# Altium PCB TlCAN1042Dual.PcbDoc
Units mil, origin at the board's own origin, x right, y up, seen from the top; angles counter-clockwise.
Board outline 1800 x 1400 mil, 4 copper layers (Top Layer, Signal Layer 1, Signal Layer 2, Bottom Layer), stack 84.834 mil thick; 33 components, 20 nets, 97 pads, 26 vias.
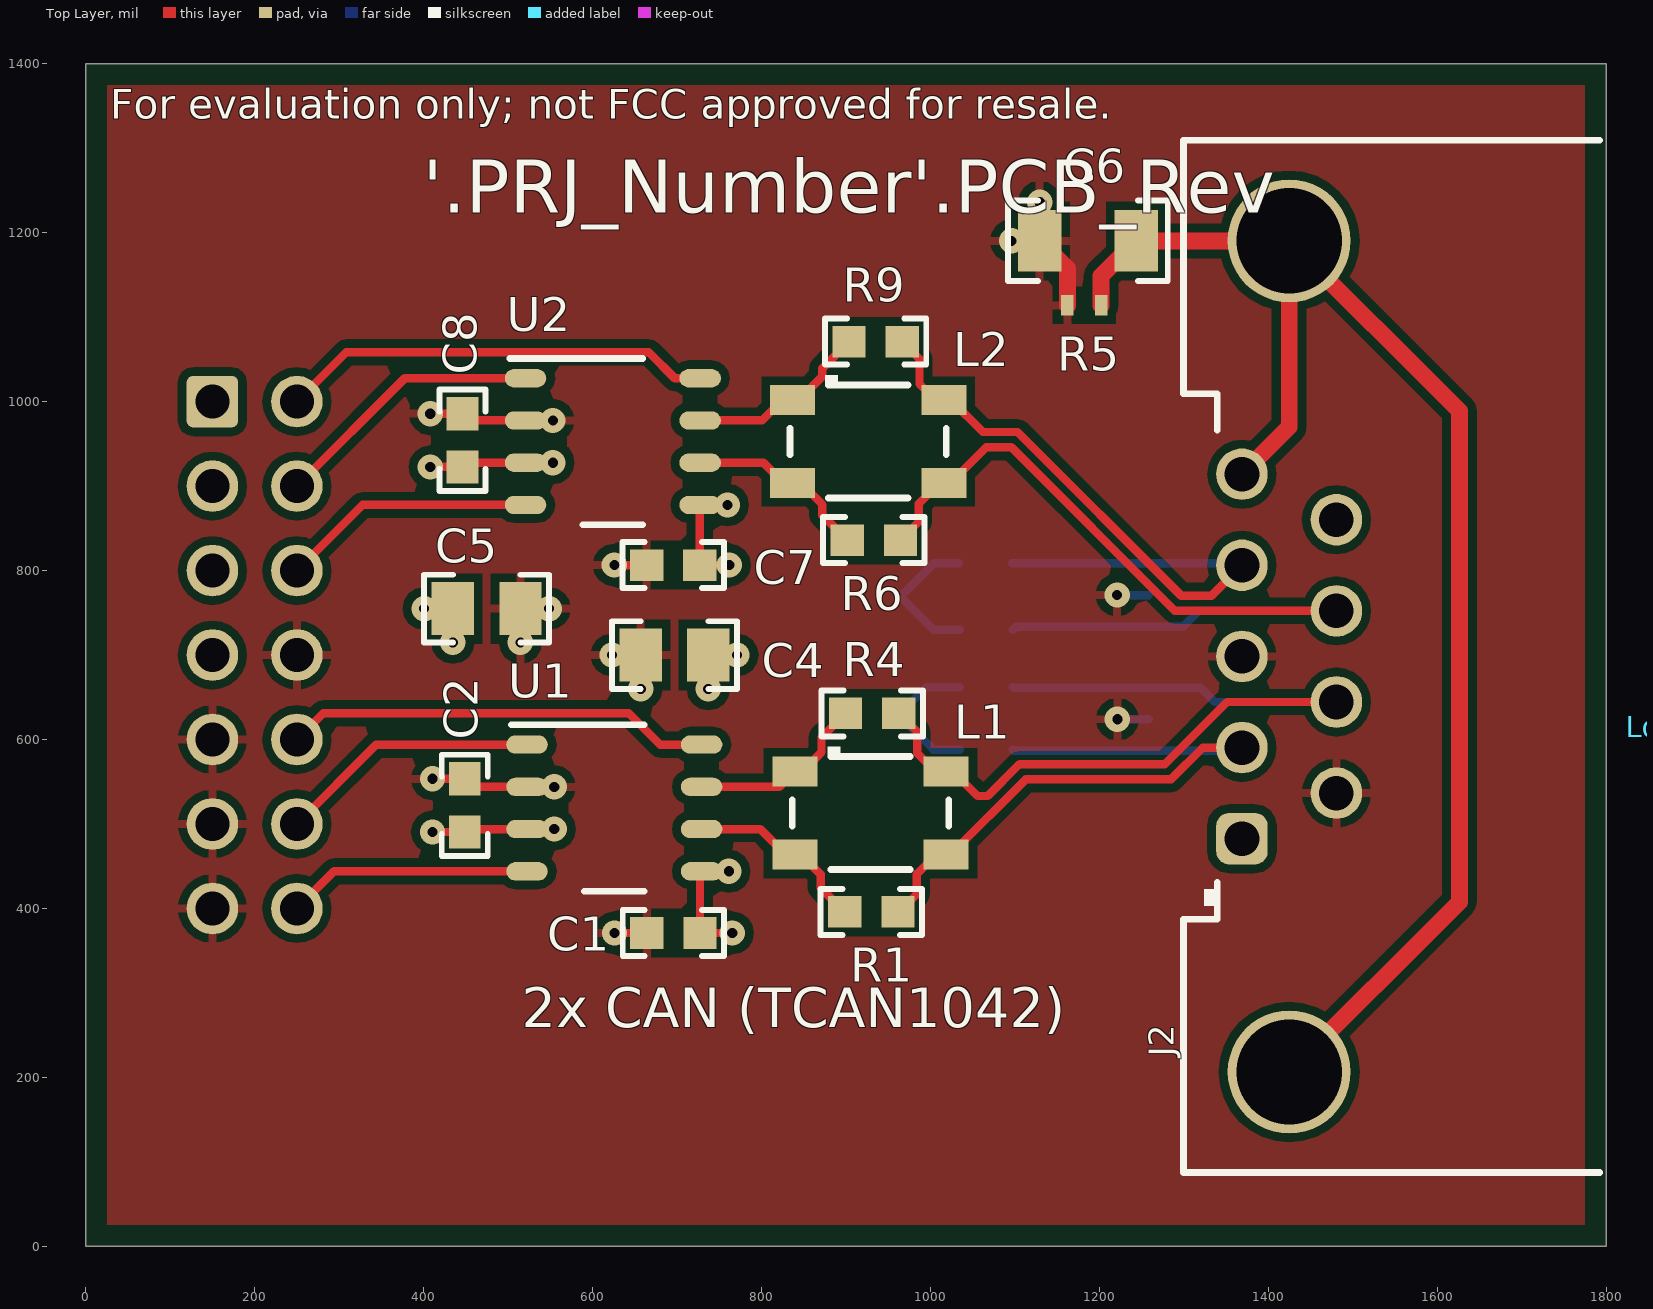
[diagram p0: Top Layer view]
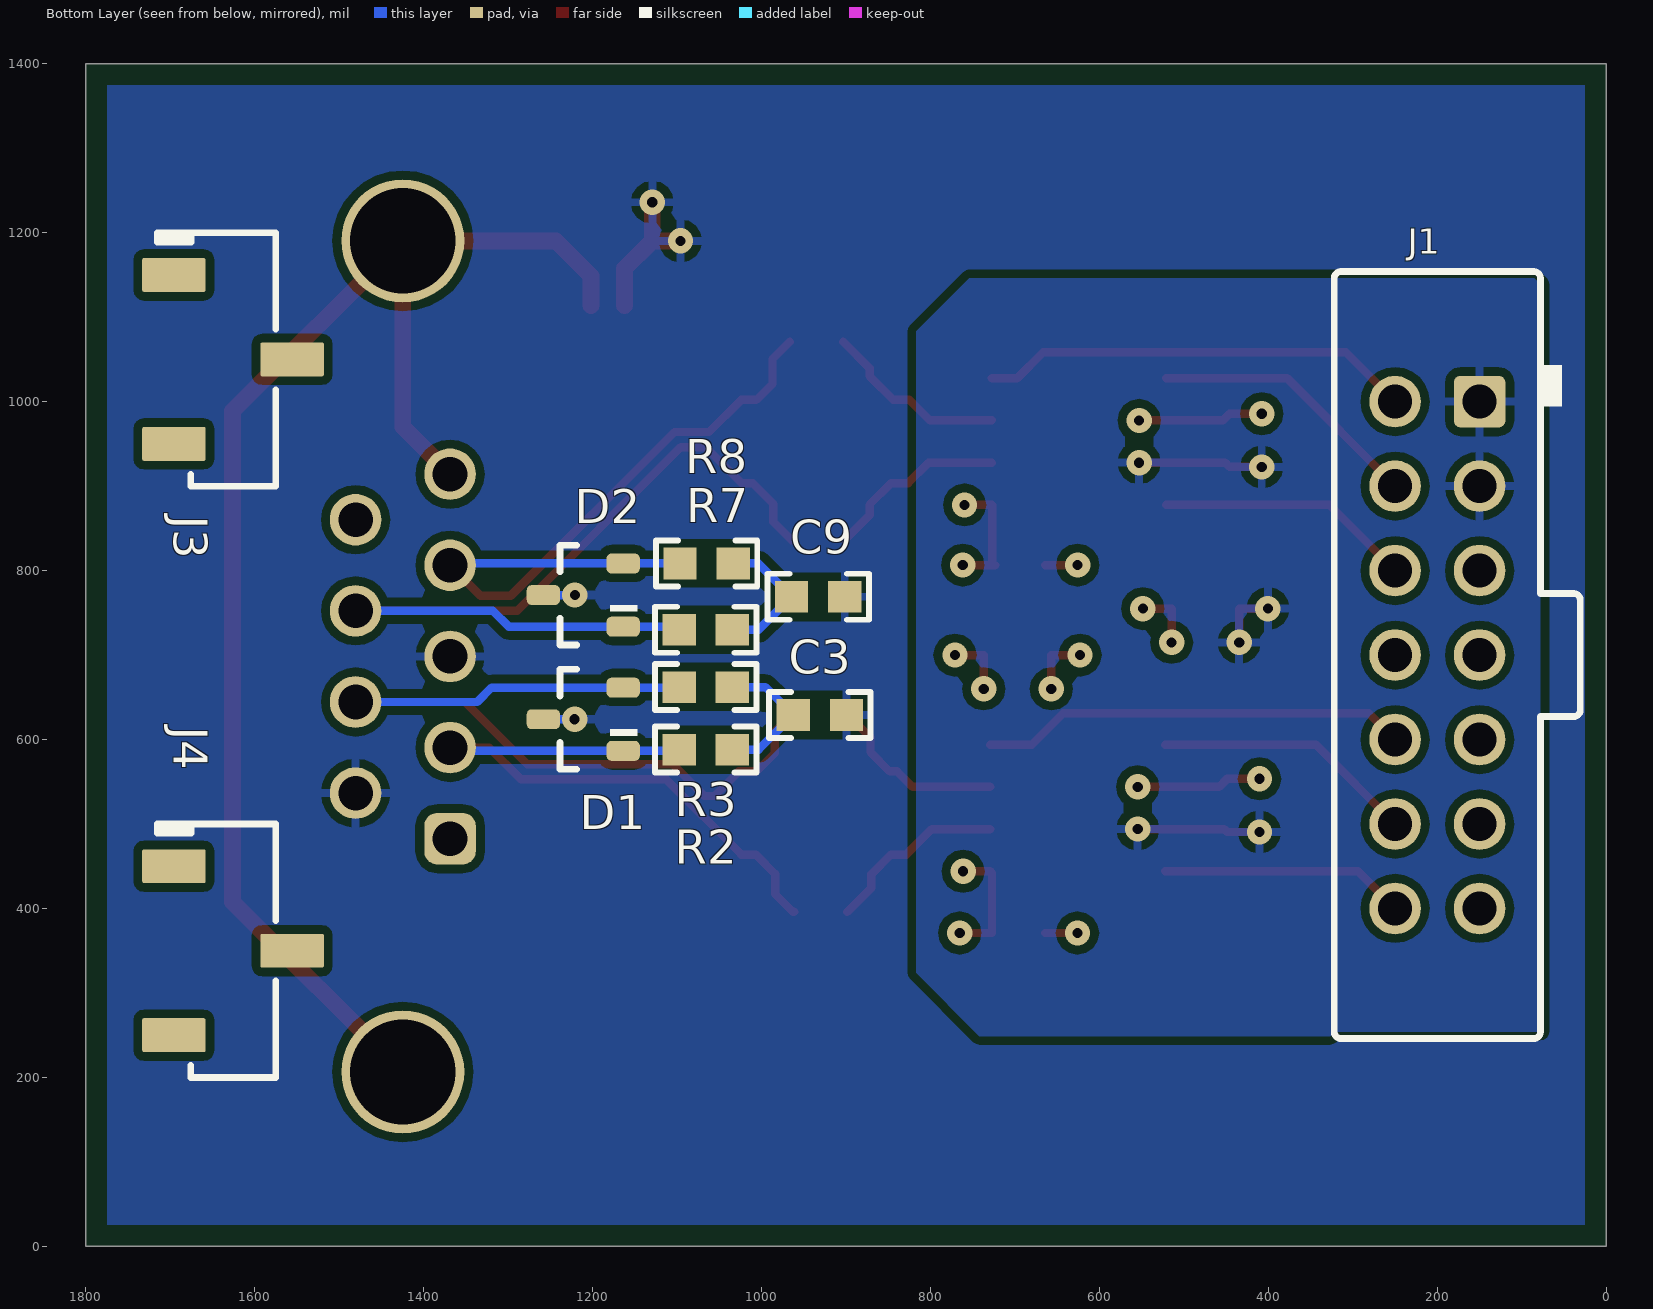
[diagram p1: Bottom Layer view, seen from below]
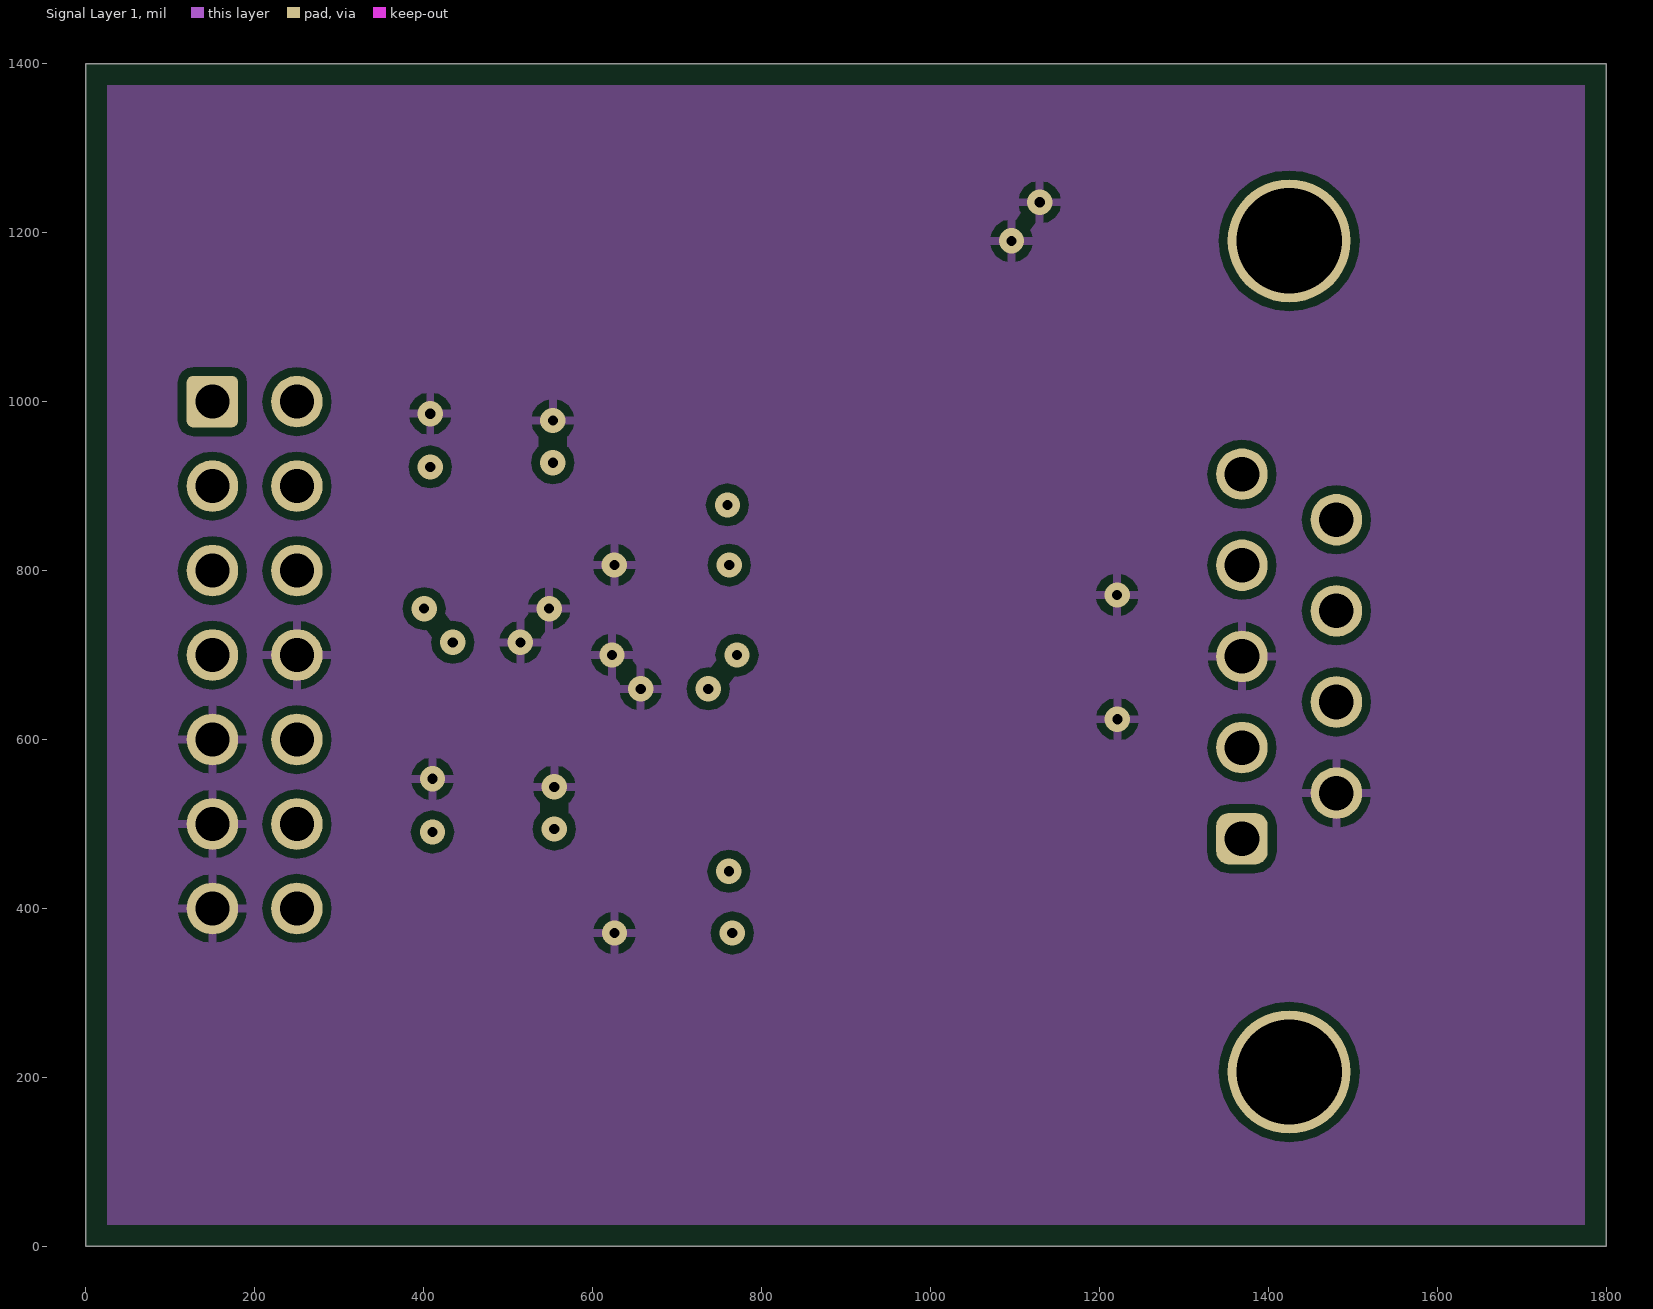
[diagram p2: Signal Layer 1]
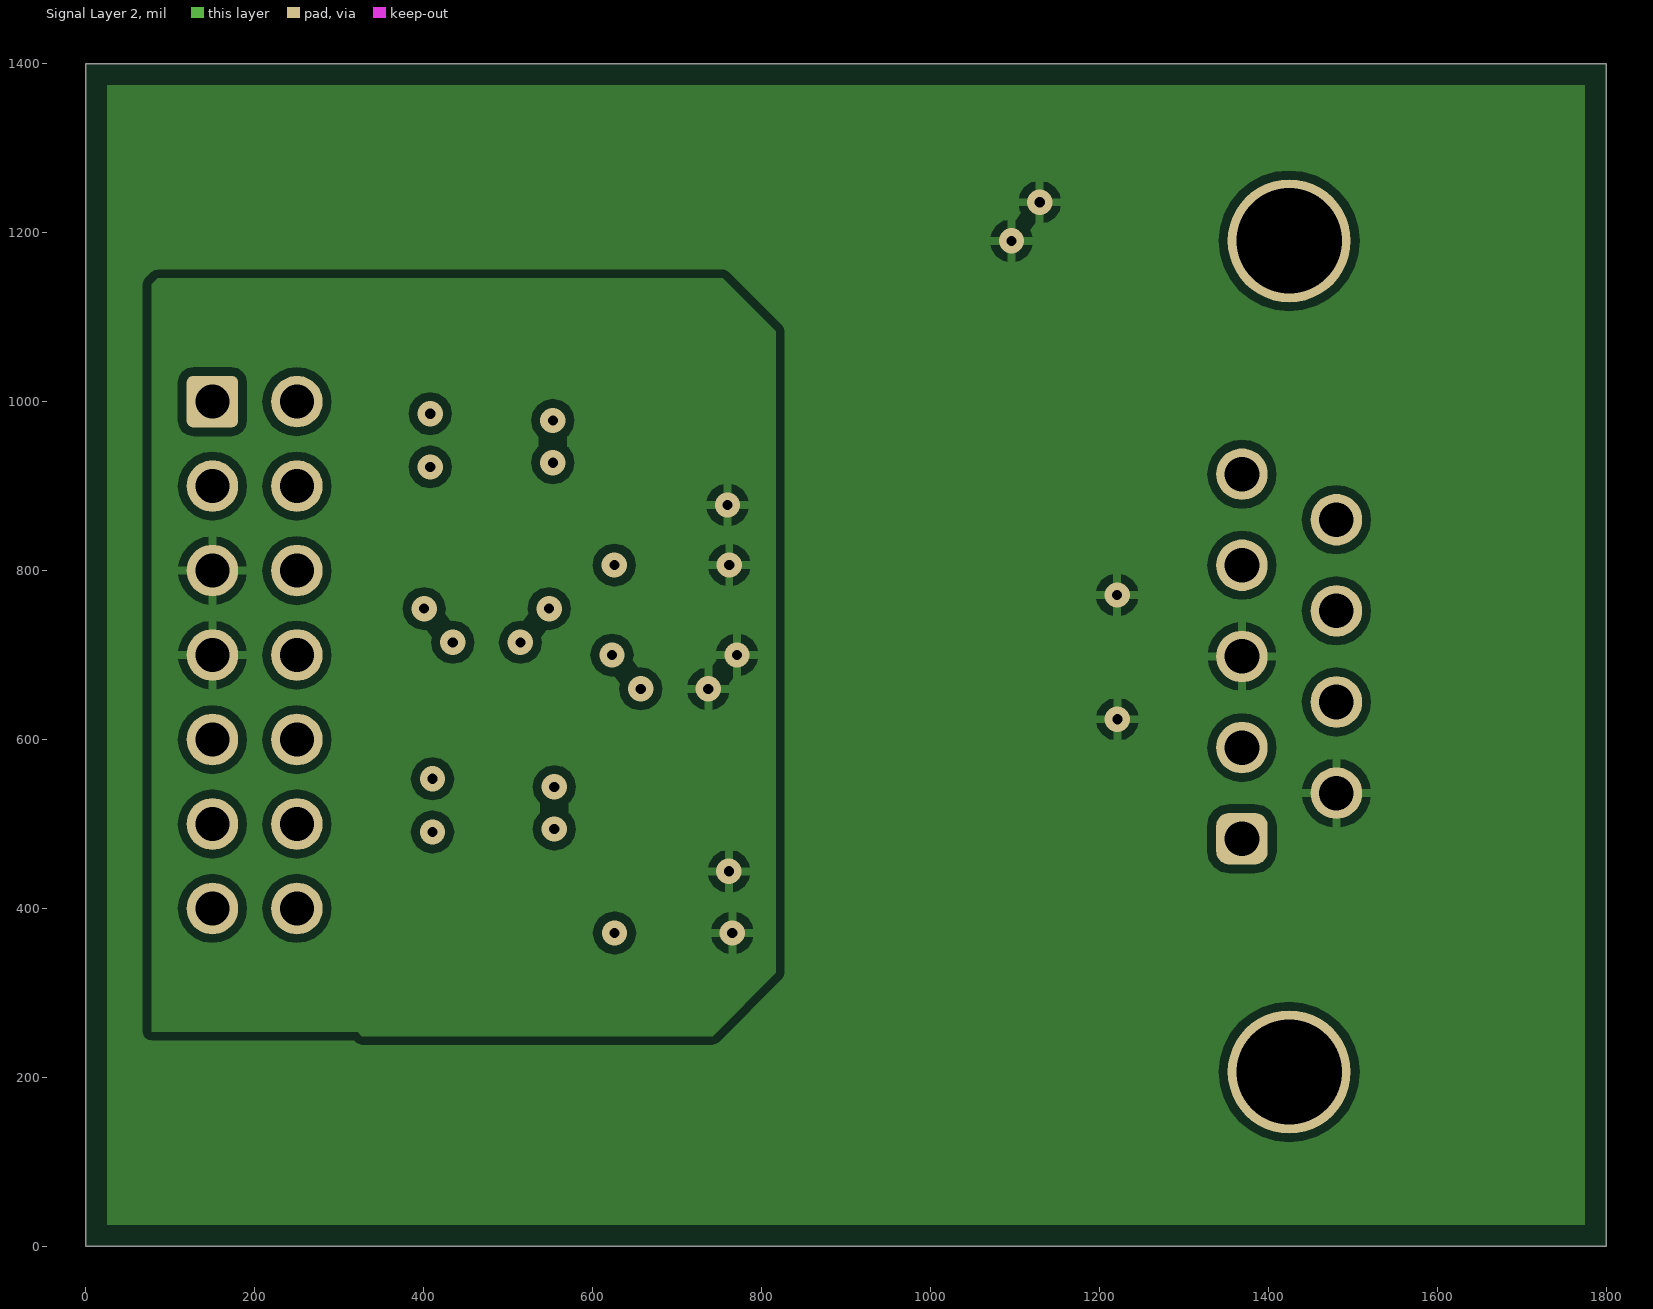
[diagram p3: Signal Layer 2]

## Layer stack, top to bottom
Top Solder: solder mask 0.4, Solder Resist, Dk 3.5
Top Layer: signal copper 1.4
Dielectric 2: dielectric 10, Dk 4.2
Signal Layer 1: signal copper 1.417
Dielectric1: core 59.2, FR-4, Dk 4.8
Signal Layer 2: signal copper 1.417
Dielectric 3: dielectric 10, Dk 4.2
Bottom Layer: signal copper 1.4
Bottom Solder: solder mask 0.4, Solder Resist, Dk 3.5

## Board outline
0,0 1800,0 1800,1400 0,1400

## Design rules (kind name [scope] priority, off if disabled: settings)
AcuteAngle [All] p1: minimum=4.50000000000000E+0001 checktracksonly=FALSE
AssemblyTestPointUsage [All] p1: valid=2
BoardOutlineClearance BoardOutlineClearance_MountingHoles [OnCopper and InComponentClass('Mounting Holes')] p1: gap=39.37 ignorepadtopadclearanceinfootprint=FALSE
BoardOutlineClearance BoardOutlineClearance_Poly [OnCopper and IsPoly] p2: gap=25 ignorepadtopadclearanceinfootprint=FALSE
BoardOutlineClearance [OnCopper and Not InComponentClass('Logo') and not InComponentClass('FiducialMark') and not InRegion(1000,500,4000,800) and not InPoly] p3: gap=75 ignorepadtopadclearanceinfootprint=FALSE
Clearance Clearance_Keepouts [((IsTrack Or IsArc) And Not InPoly) And IsFree and IsKeepOut vs ((IsTrack Or IsArc) And Not InPoly) And IsFree and IsKeepOut] p1: gap=0 ignorepadtopadclearanceinfootprint=FALSE
Clearance Clearance_Poly [InPolygon] p2: gap=10 ignorepadtopadclearanceinfootprint=TRUE
Clearance Clearance_FiducialMark [IsKeepOut and InComponentClass('FiducialMark') vs IsPad and InComponentClass('FiducialMark')] p3: gap=0 ignorepadtopadclearanceinfootprint=FALSE
Clearance [All] p4: gap=7.87 ignorepadtopadclearanceinfootprint=TRUE
ComponentClearance ComponentClearance_MountingHoles_FiducialMarks [InComponentClass('Mounting Holes') vs InComponentClass('FiducialMark')] p1: gap=50 collisioncheckmode=3 verticalgap=10 showdistances=FALSE
ComponentClearance ComponentClearance_Shunt [InComponentClass('Header') vs InComponentClass('Shunt')] p2: gap=0 collisioncheckmode=3 verticalgap=0 showdistances=FALSE
ComponentClearance ComponentClearance_Logo [InComponentClass('Logo')] p3: gap=50 collisioncheckmode=3 verticalgap=10 showdistances=FALSE
ComponentClearance ComponentClearance_ScrewToNut [(HasFootprint('NY PMS 440 0025 PH')) vs (HasFootprint('Keystone_1902C'))] p4: gap=5 collisioncheckmode=3 verticalgap=10 showdistances=FALSE
ComponentClearance ComponentClearance_MountingHoles [InComponentClass('Mounting Holes')] p5: gap=250 collisioncheckmode=3 verticalgap=100000 showdistances=FALSE
ComponentClearance ComponentClearance_SmallPassives [HasFootprint('0201*') or HasFootprint('0402*') or HasFootprint('0508') or HasFootprint('0603*') or HasFootprint('0612') or HasFootprint('0805*') or HasFootprint('0815*') or HasFootprint('0830*') or HasFootprint('1206*') or HasFootprint('1210*') or HasFootprint('1808*') or HasFootprint('1812*') or HasFootprint('1825*') or HasFootprint('2010*') or HasFootprint('2220*') or HasFootprint('2225*') or HasFootprint('2512*') or HasFootprint('2728*') or HasFootprint('3518*') vs HasFootprint('0201*') or HasFootprint('0402*') or HasFootprint('0508') or HasFootprint('0603*') or HasFootprint('0612') or HasFootprint('0805*') or HasFootprint('0815*') or HasFootprint('0830*') or HasFootprint('1206*') or HasFootprint('1210*') or HasFootprint('1808*') or HasFootprint('1812*') or HasFootprint('1825*') or HasFootprint('2010*') or HasFootprint('2220*') or HasFootprint('2225*') or HasFootprint('2512*') or HasFootprint('2728*') or HasFootprint('3518*')] p6: gap=14.96 collisioncheckmode=3 verticalgap=10 showdistances=FALSE
ComponentClearance ComponentClearance_THtoSMT [IsThruComponent vs IsSMTComponent] p7: gap=40 collisioncheckmode=3 verticalgap=30 showdistances=FALSE
ComponentClearance ComponentClearance_THtoTH [IsThruComponent vs IsThruComponent] p8: gap=30 collisioncheckmode=3 verticalgap=30 showdistances=FALSE
ComponentClearance [All] p9: gap=30 collisioncheckmode=3 verticalgap=10 showdistances=FALSE
DiffPairsRouting [All] p1: maxlimit=100 minlimit=10 mostfreqgap=10 toplayer_minwidth=15 toplayer_maxwidth=15 toplayer_prefwidth=15 midlayer1_minwidth=15 midlayer1_maxwidth=15 midlayer1_prefwidth=15 midlayer2_minwidth=15 midlayer2_maxwidth=15 midlayer2_prefwidth=15 bottomlayer_minwidth=15 bottomlayer_maxwidth=15 bottomlayer_prefwidth=15 maxuncoupledlength=1000
FabricationTestPointUsage TestPointUsage [All] p1: valid=2 allowmultiple=FALSE
FabricationTestpoint Testpoint [All] p1: side=3 testpointundercomponent=TRUE minsize=40 maxsize=100 preferedsize=60 minholesize=0 maxholesize=40 preferedholesize=32 testpointgrid=1 allowsidetop=TRUE allowsidebottom=TRUE usegrid=TRUE gridtolerance=0.01
FanoutControl Fanout_LCC [IsLCC] p1: bgadir=Out bgaviamode=Centered fanoutstyle=Auto fanoutdirection=Alternating viagrid=1 // Fanout_LCC (Default Rule)
FanoutControl Fanout_BGA [IsBGA] p2: bgadir=Out bgaviamode=Centered fanoutstyle=Auto fanoutdirection=Alternating viagrid=1 // Fanout_BGA (Default Rule)
FanoutControl Fanout_Default [All] p4: bgadir=Out bgaviamode=Centered fanoutstyle=Auto fanoutdirection=Alternating viagrid=1 // Fanout_Default (Default Rule)
FanoutControl Fanout_Small [(CompPinCount < 5)] p5: bgadir=Out bgaviamode=Centered fanoutstyle=Auto fanoutdirection=OutThenIn viagrid=1 // Fanout_Small (Default Rule)
HoleSize [All] p1: absolutevalues=TRUE maxlimit=251 minlimit=7.87 maxpercent=80.000 minpercent=20.000
MinimumAnnularRing MinimumAnnularRing_ThermalPadVias [IsVia and InAnyComponent] p1: minimumring=5.91
MinimumAnnularRing [All] p2: minimumring=7.87
MinimumSolderMaskSliver MinimumSolderMaskSliver_Logo [InComponentClass('Logo') vs InComponentClass('Logo')] p1: minsoldermaskwidth=0.7
MinimumSolderMaskSliver [All] p2: minsoldermaskwidth=3.94
PlaneConnect [All] p1: planeconnectstyle=Relief reliefexpansion=10 reliefentries=4 reliefconductorwidth=10 reliefairgap=10
PolygonConnect [All] p1: connectstyle=Relief reliefconductorwidth=10 reliefentries=4 polygonreliefangle="90 Angle" airgapwidth=10
RoutingVias ThermalPadVias [IsVia and InAnyComponent] p1: holewidth=7.87 width=19.68 viastyle="Through Hole" minholewidth=7.87 minwidth=19.68 maxholewidth=12.99 maxwidth=23.62
RoutingVias [All] p2: holewidth=16 width=34 viastyle="Through Hole" minholewidth=7.87 minwidth=26 maxholewidth=40 maxwidth=65
SilkToBoardRegionClearance [Not ((IsComment or IsDesignator) And (Hide <> 'False')) and not InRegion(1000,500,4000,800)] p1:
SilkToSilkClearance SilkToSilkClearance_Pb-FreeLogo [(HasFootprint('Pb-Free_Overlay_Medium') OR HasFootprint('Pb-Free_Overlay_Small')) vs (HasFootprint('Pb-Free_Overlay_Medium') OR HasFootprint('Pb-Free_Overlay_Small'))] p1: silktosilkclearance=0
SilkToSilkClearance [All] p2: silktosilkclearance=3.94
SilkToSolderMaskClearance SilkToComponentPadClearance [(IsPad or IsFill or IsRegion) and InAnycomponent] p1: minsilkscreentomaskgap=5 clearancetoexposedcopper=TRUE
SilkToSolderMaskClearance "Silk to Solder Mask Opening" [All] p2: minsilkscreentomaskgap=3.94 clearancetoexposedcopper=FALSE
SolderMaskExpansion [All] p1: expansion=1.97
UnRoutedNet [All] p1: checkbadconnections=TRUE
Width [All] p1: maxlimit=100 minlimit=6 preferedwidth=10 checkconnectedcopper=TRUE
14 further rules are at their usual default settings.

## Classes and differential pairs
component class AssemblyNote: ZZ1 ZZ2 ZZ3 ZZ4

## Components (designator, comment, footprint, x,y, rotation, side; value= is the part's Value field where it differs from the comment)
C1 "GRM188R72A104KA35D" 0603 695.69,371 r180 top value=0.1uF
C2 "GRM188R72A104KA35D" 0603 448.69,522 r90 top value=0.1uF
C3 "CGA3E2X7R2A472K080AA" 0603 931,629 r0 bottom value=4700pF
C4 "CL21B106KOQNNNE" 0805_HV 697,700 r180 top value=10uF
C5 "CL21B106KOQNNNE" 0805_HV 474.57,755 r0 top value=10uF
C6 "12061C103JAT2A" 1206 1186.39,1190.3 r180 top value=0.01uF
C7 "GRM188R72A104KA35D" 0603 695.52,806.52 r180 top value=0.1uF
C8 "GRM188R72A104KA35D" 0603 446.03,954.18 r90 top value=0.1uF
C9 "CGA3E2X7R2A472K080AA" 0603 933,769 r0 bottom value=4700pF
D1 "NUP2105LT1G" SOT-23 1211,624 r0 bottom value=24V
D2 "NUP2105LT1G" SOT-23 1211,771 r0 bottom value=24V
J1 "SFH11-PBPC-D07-ST-BK" Sullins_SFH11-xxxC-D07-ST-BK 200,700 r270 bottom locked
J2 "5747840-5" TE_5747840-5 1800,698.37 r90 top locked
J3 "SSM-103-S-SV" Samtec_SSM-103-x-SV 1625.62,1050 r270 bottom locked
J4 "SSM-103-S-SV" Samtec_SSM-103-x-SV 1625.62,350 r270 bottom locked
L1 "ACT45B-101-2P-TL003" ACT45B 929,513 r0 top value=100uH
L2 "ACT45B-101-2P-TL003" ACT45B 926.2,952.77 r0 top value=100uH
Logo2 "FCC disclaimer" FCC_disclaimer 1876,615 r90 top
R1 "RMCF0603ZT0R00" 0603 930,396 r0 top value=0
R2 "CRCW060360K4FKEA" 0603 1066,588 r0 bottom value=60.4k
R3 "CRCW060360K4FKEA" 0603 1066,662 r180 bottom value=60.4k
R4 "RMCF0603ZT0R00" 0603 931,631 r0 top value=0
R5 "ERJ-2RKF1004X" 0402S 1182,1114 r0 top value=1.00Meg
R6 "RMCF0603ZT0R00" 0603 933,836 r0 top value=0
R7 "CRCW060360K4FKEA" 0603 1066,730 r0 bottom value=60.4k
R8 "CRCW060360K4FKEA" 0603 1065,808.4 r180 bottom value=60.4k
R9 "RMCF0603ZT0R00" 0603 935,1071 r0 top value=0
U1 "TCAN1042GVDRQ1" D0008A_L 625.71,519 r0 top
U2 "TCAN1042GVDRQ1" D0008A_L 624,952.68 r0 top
ZZ1 "This Assembly Note is for PCB labels only" AssemblyNoteLabel 185,3938 r0 top
ZZ2 "These assemblies are ESD sensitive, ESD precautions shall be observed." AssemblyNote 185,3829.11 r0 top
ZZ3 "These assemblies must be clean and free from flux and all contaminants. Use of no clean flux is not acceptable." AssemblyNote 185,3740.56 r0 top
ZZ4 "These assemblies must comply with workmanship standards IPC-A-610 Class 2, unless otherwise specified." AssemblyNote 185,3652 r0 top

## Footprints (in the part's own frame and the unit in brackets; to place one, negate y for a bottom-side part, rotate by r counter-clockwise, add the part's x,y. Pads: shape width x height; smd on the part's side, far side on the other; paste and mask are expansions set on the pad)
0402S [mil] "Based on C0402S footprint from PADS legacy"
  rect 15x24 smd: 1(-20,0) 2(20,0)
  body extent -22,-12 22,12, height 24
0603 [mm] "0603 from SM-752 data"
  rect 1x0.95 smd: 1(-0.8,0) 2(0.8,0)
  silkscreen extent -1.52,-0.69 1.52,0.69, body extent -0.87,-0.47 0.87,0.47, height 1
0805_HV [mil] "0805 with 30mil clearance between pads"
  rect 50x63 smd: 1(-40,0) 2(40,0)
  silkscreen extent -74,-40 74,40, body extent -43,-29 43,29, height 57
1206 [mm] "1206 from SM-752 data"
  rect 1.3x1.85 smd: 1(-1.45,0) 2(1.45,0)
  silkscreen extent -2.4,-1.21 2.4,1.21, body extent -1.7,-0.9 1.7,0.9, height 1.35
ACT45B [mm] "SMD, 4-Leads, Body 4.7 x 3.7 mm"
  rect 1.35x0.9 smd: 1(-2.275,1.25) 2(-2.275,-1.25) 3(2.275,-1.25) 4(2.275,1.25)
  silkscreen extent -2.35,-1.7 2.35,2, body extent -2.35,-1.7 2.35,1.7, height 3
AssemblyNote [mil] "Assembly Note"
AssemblyNoteLabel [mil] "Assembly Note for PCB Labels"
D0008A_L [mm] "SOIC, 8-Leads, Body 4.9x3.9mm, Pitch 1.27mm, IPC High Density"
  oval 1.25x0.55 smd: 1(-2.625,1.905) 2(-2.625,0.635) 3(-2.625,-0.635) 4(-2.625,-1.905) 5(2.625,-1.905) 6(2.625,-0.635) 7(2.625,0.635) 8(2.625,1.905)
  silkscreen extent -3.1,-2.5 0.9,2.5, body extent -3,-2.45 3,2.45, height 1.63
FCC_disclaimer [mil]
Samtec_SSM-103-x-SV [mm] "Receptacle, 2.54mm, 3x1, SMT"
  rrect10% 1.02x1.905 smd: 1(-2.54,-1.777) 2(0,1.777) 3(2.54,-1.777)
  silkscreen extent -3.81,-2.27 3.81,1.28, body extent -3.81,-2.29 3.81,2.29, height 7.51
SOT-23 [mm] "SOT23, 3-Leads, Body 2.9x1.3mm, Pitch 0.95mm, Lead Span 2.5mm, IPC Medium Density"
  rrect50% 1x0.6 smd: 1(-1.2,0.95) 2(-1.2,-0.95) 3(1.2,0)
  silkscreen extent -1.62,-1.5 0.7,1.5, body extent -1.16,-1.45 1.21,1.45, height 1
Sullins_SFH11-xxxC-D07-ST-BK [mm] "Receptacle, 2.54mm, 7x2, TH"
  rrect25% 1.55x1.55 hole 1.02: 1(-7.62,1.27)
  round 1.55 hole 1.02: 2(-7.62,-1.27) 3(-5.08,1.27) 4(-5.08,-1.27) 5(-2.54,1.27) 6(-2.54,-1.27) 7(0,1.27) 8(0,-1.27) 9(2.54,1.27) 10(2.54,-1.27) 11(5.08,1.27) 12(5.08,-1.27) 13(7.62,1.27) 14(7.62,-1.27)
  silkscreen extent -11.53,-3.1 11.53,4.3, body extent -11.53,-3.1 11.53,4.3, height 8.71
TE_5747840-5 [mm] "D-Sub, 2.74mm, 9 Position, R/A, TH"
  rrect50% 1.55x1.55 hole 1.04: 1(-5.48,10.954)
  round 1.55 hole 1.04: 2(-2.74,10.954) 3(0,10.954) 4(2.74,10.954) 5(5.48,10.954) 6(-4.11,8.114) 7(-1.37,8.114) 8(1.37,8.114) 9(4.11,8.114)
  round 3.7 hole 3.17: 10(12.495,9.534) 11(-12.495,9.534)
  silkscreen extent -15.52,0.2 15.52,12.71, body extent -15.52,-5.89 15.52,12.71, height 12.55

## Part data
C1 C2 C7 C8: library part CMP-0007469-4, "CAP, CERM, 0.1 uF, 100 V, +/- 10%, X7R, 0603", Cap_Case=0603, Manufacturer=MuRata, Supplier Part Number 1=490-3285-1-ND, TempCo=X7R, Tolerance_%=10%, Value1=Unknown, Value2=100V, ValueDisplayed=0.1uF
C3 C9: library part CMP-0007088-4, "CAP, CERM, 4700 pF, 100 V, +/- 10%, X7R, AEC-Q200 Grade 1, 0603", Cap_Case=0603, Manufacturer=TDK, Supplier Part Number 1=445-5810-1-ND, TempCo=X7R, Tolerance_%=10%, Value1="0.469862 ohm", Value2=100V, ValueDisplayed=4700pF
C4 C5: library part CMP-0007995-2, "CAP, CERM, 10 uF, 16 V, +/- 10%, X7R, 0805", Cap_Case=0805, Manufacturer="Samsung Electro-Mechanics", TempCo=X7R, Tolerance_%=10%, Value1=Unknown, Value2=16V, ValueDisplayed=10uF
C6: library part CMP-0008484-2, "CAP, CERM, 0.01 uF, 100 V, +/- 5%, X7R, 1206", Cap_Case=1206, Manufacturer=AVX, Supplier Part Number 1=478-3783-1-ND, TempCo=X7R, Tolerance_%=5%, Value1="0.119 ohm", Value2=100V, ValueDisplayed=0.01uF
D1 D2: library part CMP-0005919-2, "Diode, TVS, Bi, 24 V, SOT-23", Manufacturer="ON Semiconductor", Power_W=350mW, Supplier Part Number 1=NUP2105LT1GOSCT-ND, Value1=0.35W
J1: library part CMP-0054668-1, "Receptacle, 2.54mm, 7x2, Gold, Black, TH", Color=Black, Current_A=3A, Manufacturer="Sullins Connector Solutions", Supplier Part Number 1=S9195-ND, Voltage_V=1kV
J2: library part CMP-0054938-4, "D-Sub, 2.74mm, 9 Position, R/A, TH", Color=Black, Manufacturer="TE Connectivity", Supplier Part Number 1=A32093-ND
J3 J4: library part CMP-0078183-1, "Receptacle, 2.54mm, 3x1, Gold with Tin tail, SMT", Color=Black, Current_A=5.2A, Manufacturer=Samtec, Supplier Part Number 1=SAM1152-03-ND, Voltage_V=405V
L1 L2: library part CMP-0062430-2, "Inductor, Ferrite, 100 uH, 0.15 A, 2 ohm, SMD", Manufacturer=TDK, Supplier Part Number 1=445-3959-1-ND, Value1="2 ohm", Value2=0.15A, ValueDisplayed=100uH
Logo2: library part CMP-0074847-1, "FCC_disclaimer"
R1 R4 R6 R9: library part CMP-0023343-3, "RES, 0, 1%, 0.1 W, AEC-Q200 Grade 0, 0603", Manufacturer="Stackpole Electronics Inc", Power_W=100mW, Supplier Part Number 1=RMCF0603ZT0R00CT-ND, TempCo=ppm/C, Tolerance_%=1%, Value2=0.1W, Value_Code=0
R2 R3 R7 R8: library part CMP-0022532-4, "RES, 60.4 k, 1%, 0.1 W, AEC-Q200 Grade 0, 0603", Manufacturer=Vishay-Dale, Power_W=100mW, Supplier Part Number 1=541-60.4KHCT-ND, TempCo="100 ppm/C", Tolerance_%=1%, Value2=0.1W, Value_Code=60k4, ValueDisplayed=60.4k
R5: library part CMP-0026660-1, "RES, 1.00 M, 1%, 0.1 W, 0402", Manufacturer=Panasonic, Power_W=100mW, Supplier Part Number 1=P1.00MLCT-ND, TempCo="100 ppm/C", Tolerance_%=1%, Value2=0.1W, Value_Code=1M00, ValueDisplayed=1.00M
U1 U2: library part CMP-0075989-1, "Automotive Fault Protected CAN Transceiver With Flexible Data-Rate, D0008A (SOIC-8)", Alternate Manufacturer="Texas Instruments", Alternate PartNumber=TCAN1042GVDQ1
ZZ1: library part CMP-0003616-3
ZZ2: library part CMP-0077236-1
ZZ3: library part CMP-0077237-1
ZZ4: library part CMP-0077238-1

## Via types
v1: diameter 30, hole 12, Top Layer to Bottom Layer, tented both sides, 26 vias

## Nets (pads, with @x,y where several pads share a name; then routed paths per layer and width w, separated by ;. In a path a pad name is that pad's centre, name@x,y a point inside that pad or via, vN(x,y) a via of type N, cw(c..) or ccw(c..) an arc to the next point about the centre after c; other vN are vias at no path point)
+3V3: C1.1 C4.1 C7.1 J1.5 J1.7 U1.5 U2.5 | length 360.1
  Top Layer w10: C7.1@723.57,806.52 v1(761.77,806.52) ; C7.1 727.02,877.36 U2.5 v1(759.68,877.68) ; v1(737,660) C4.1 v1(771,700) ; v1(761.4,444) U1.5 727.19,442.13 C1.1 v1(765.39,371)
+5V0: C2.1 C5.1 C8.1 J1.1 J1.3 U1.3 U2.3 | length 366.9
  Top Layer w10: v1(400.57,755) C5.1 v1(434.57,715) ; v1(407.83,922.68) C8.1 451.03,927.68 U2.3 v1(552.99,927.68) ; v1(410.5,490.5) C2.1 452.19,494 U1.3 v1(554.7,494)
CANH_BUS: D1.2 J2.7 L1.4 R3.1 R4.2 | length 1009.9
  Top Layer w10: R4.2 984.49,609 984.49,583.53 1005.81,562.21 L1.4 1026.79,562.21 1055.86,533.14 1067.86,533.14 1105.6,570.87 1277.51,570.87 1351.06,644.43 J2.7
  Bottom Layer w10: R3.1 1098.09,661.4 D1.2 1319.6,661.4 1336.57,644.43 J2.7
CANH_BUS2: D2.2 J2.4 L2.4 R8.1 R9.2 | length 832.2
  Top Layer w10: R9.2 987,1050.5 987,1021 1006.02,1001.98 L2.4 1024.02,1001.98 1062,964 1103,964 1296.82,770.18 1332.67,770.18 J2.4
  Bottom Layer w10: R8.1 D2.2 1366.57,808.4 J2.4
CANL_BUS: D1.1 J2.2 L1.3 R1.2 R2.2 | length 775.1
  Top Layer w10: R1.2 962.72,396 984,417.28 984,441 1006.79,463.79 L1.3 1023.79,463.79 1113,553 1284.91,553 1322.4,590.49 J2.2
  Bottom Layer w10: R2.2 1098.9,586.6 D1.1 1364.84,586.6 J2.2
CANL_BUS2: D2.1 J2.8 L2.3 R6.2 R7.2 | length 1046.8
  Top Layer w10: R6.2 986,857.5 986,879 1010.56,903.56 L2.3 1023.56,903.56 1066.13,946.13 1095.6,946.13 1289.42,752.31 J2.8
  Bottom Layer w10: R7.2 1101.09,733.6 D2.1 1299.2,733.6 1317.9,752.31 J2.8
GND: C1.2 C2.2 C3.1 C4.2 C5.2 C6.2 C7.2 C8.2 C9.1 D1.3 D2.3 J1.8 J1.9 J1.11 J1.13 J2.3 J2.6 R5.1 U1.2 U2.2 | length 764.4
  Top Layer w10: v1(407.83,985.68) C8.2 454.02,977.68 U2.2 v1(552.99,977.68) ; v1(410.5,553.5) C2.2 458.19,544 U1.2 v1(554.7,544) ; v1(514.57,715) C5.2 v1(548.57,755) ; v1(623,700) C4.2 v1(657,660) ; v1(625.83,806.52) C7.2 ; v1(626,371) C1.2
  Top Layer w20: v1(1095.89,1190.3) C6.2 ; v1(1129.31,1235.97) C6.2 ; R5.1 1162,1157.6 C6.2
  Bottom Layer w10: v1(1221,771) D2.3 ; v1(1221.24,624) D1.3@1258.49,624
NetC3_2: C3.2 R2.1 R3.2 | length 174.7
  Bottom Layer w10: R2.1 1003.5,588 C3.2 995.5,662 R3.2
NetC9_2: C9.2 R7.1 R8.2 | length 171.5
  Bottom Layer w10: R8.2 1003.9,808.4 C9.2 1003.5,730 R7.1
NetL1_1: L1.1 R4.1 U1.7 | length 216.8
  Top Layer w10: U1.7 821.22,544 L1.1 848.29,562.21 871.02,584.94 871.02,602.51 R4.1
NetL1_2: L1.2 R1.1 U1.6 | length 219.4
  Top Layer w10: U1.6 798.44,494 828.65,463.79 L1.2 846.71,463.79 870.02,440.48 870.02,424.49 R1.1
NetL2_1: L2.1 R9.1 U2.7 | length 220.4
  Top Layer w10: U2.7 800.68,977.68 824.98,1001.98 L2.1 843.98,1001.98 872,1030 872,1039.5 R9.1
NetL2_2: L2.2 R6.1 U2.6 | length 219.5
  Top Layer w10: U2.6 802.32,927.68 826.44,903.56 L2.2 846.44,903.56 871.98,878.02 871.98,865.53 R6.1
nSTB: J1.10 U1.8 | length 507.2
  Top Layer w10: J1.10 281,631 643,631 680,594 U1.8
nSTB2: J1.2 U2.8 | length 514.2
  Top Layer w10: J1.2 308.32,1058.32 666.68,1058.32 697.32,1027.68 U2.8
RxD: J1.14 U1.4 | length 290.6
  Top Layer w10: J1.14 294,444 U1.4
RxD2: J1.6 U2.4 | length 302.8
  Top Layer w10: J1.6 327.68,877.68 U2.4
SHIELD_GND: C6.1 J2.5 J2.10 J2.11 R5.2 | length 1724.6
  Top Layer w20: R5.2 1202,1148.82 C6.1 J2.10 ; J2.5 1424.64,970.02 J2.10 ; J2.11 1626,407.8 1626,988.94 J2.10
TxD: J1.12 U1.1 | length 311.3
  Top Layer w10: J1.12 344,594 U1.1
TxD2: J1.4 U2.1 | length 323.5
  Top Layer w10: J1.4 377.68,1027.68 U2.1
pads on no net: J2.1 J2.9 J3.1 J3.2 J3.3 J4.1 J4.2 J4.3

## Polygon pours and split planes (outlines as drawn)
GND on Bottom Layer "BOTTOM_LAYER_GND_P006" (solid, remove dead copper, pour order 6): 0,1400 0,0 1800,0 1800,1400
+5V0 on Bottom Layer "BOTTOM_LAYER_+5V0_P000" (solid, remove dead copper, pour order 0): 77.95,1146.06 77.95,253.94 322.05,253.94 326.98,249 742,249 817,324 817,1083 754,1146
GND on Signal Layer 1 "SIGNAL_LAYER_1_GND_P004" (solid, remove dead copper, pour order 4): 0,1400 0,0 1800,0 1800,1400
GND on Signal Layer 2 "SIGNAL_LAYER_2_GND_P010" (solid, remove dead copper, pour order 10): 1,1398 1,-2 1801,-2 1801,1398
+3V3 on Signal Layer 2 "SIGNAL_LAYER_2_+3V3_P002" (solid, remove dead copper, pour order 2): 77.95,1146.06 77.95,253.94 322.05,253.94 326.98,249 742,249 817,324 817,1083 754,1146
GND on Top Layer "TOP_LAYER_GND_P008" (solid, remove dead copper, pour order 8): 1,1398 1,-2 1801,-2 1801,1398

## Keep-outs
Keep-Out Layer:
  text ".Layer_Name" at 577,-858.49 h60

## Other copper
Top Layer:
  text ".Layer_Name" at 577,-858.49 h60
Bottom Layer:
  text ".Layer_Name" at 577,-858.49 h60

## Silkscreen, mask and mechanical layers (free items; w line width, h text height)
Top Overlay:
  text "'.PRJ_Number'.PCB_Rev" at 399,1202.58 h108.27
  text "2x CAN (TCAN1042)" at 516,244.16 h80
  text ".Layer_Name" at 577,-858.49 h60
Bottom Overlay:
  text ".Layer_Name" at 577,-858.49 h60
Top Paste:
  text ".Layer_Name" at 577,-858.49 h60
Bottom Paste:
  text ".Layer_Name" at 577,-858.49 h60
Top Solder:
  text ".Layer_Name" at 577,-858.49 h60
  text ".Layer_Name" at 577,-858.49 h60
Bottom Solder:
  text ".Layer_Name" at 577,-858.49 h60
Drill Guide:
  text ".Layer_Name" at 577,-858.49 h60
M1 Board Outline:
  the board outline again, w10
  text ".Layer_Name" at 577,-858.49 h60
M2 Board Dimensions:
  rectangle: 0,-275 125,-150
  rectangle: 125,-400 500,-275
  lines w7: 0,-275 1000,-275 ; 125,-400 125,-150 ; 250,-400 250,-150 ; 500,-400 500,-150 ; 750,-400 750,-150 ; 0,-400 1000,-400 1000,-150 0,-150 0,-400
  text ".Layer_Name" at 577,-858.49 h60
M3 3D STEP Top:
  text ".Layer_Name" at 577,-858.49 h60
M4 3D STEP Bottom:
  text ".Layer_Name" at 577,-858.49 h60
M5 Assembly Top:
  lines w10: -292,-930.17 6308,-930.17 ; -292,-726.83 6310,-726.83 ; -292,-523.5 -292,-1133.5 3713,-1133.5 6310,-1133.5 6310,-523.5 -291.5,-523.5 -291.5,-1133.5 1284,-1133.5 ; 2173,-1133.5 2173,-523.5 ; 3440,-726.83 3440,-523.5 ; 4280,-726.83 4280,-523.5 ; 4902,-1140 4902,-937.17
  text "COMPONENTS MARKED 'DNP' SHOULD NOT BE POPULATED." at 1153.5,-318.5 h60
  text "ASSEMBLY VARIANT:" at 1153,-434 h60
  text ".VariantName" at 2189,-434 h60
  text "PCB VIEWED FROM TOP SIDE" at -228.5,-655.67 h60
  text "BOARD #:" at 2248,-655.67 h60
  text ".PRJ_Number" at 2793.5,-655.67 h60
  text "REV:" at 3638,-655.67 h60
  text ".PCB_Rev" at 3929.5,-655.67 h60
  text "SVN REV:" at 4476,-655.67 h60
  text ".VersionControl_RevNumber" at 4982,-655.67 h60
  text "TID #:" at 2248,-859 h60
  text ".TID" at 2793.5,-859 h60
  text "PLOT NAME =" at -228.5,-1064.34 h60
  text ".plot_File_Name" at 577,-1064.34 h60
  text "GENERATED    :" at 2250,-1064.34 h60
  text ".Print_Date" at 3119.5,-1064.34 h60
  text ".Print_Time" at 3848.5,-1064.34 h60
  text "TEXAS INSTRUMENTS" at 5113,-1064.34 h60
M6 Assembly Bottom:
  lines w10: -292.5,-727.33 6309.5,-727.33 ; -290.5,-930.67 6309.5,-930.67 ; 1115.5,-1140.5 1115.5,-937.67 ; 1737.5,-727.33 1737.5,-524 ; 2577.5,-727.33 2577.5,-524 ; 3844.5,-1134 3844.5,-524 ; 4733.5,-1134 6309,-1134 6309,-524 -292.5,-524 -292.5,-1134 2304.5,-1134 6309.5,-1134 6309.5,-524
  text "COMPONENTS MARKED 'DNP' SHOULD NOT BE POPULATED." at 6102,-318 h60
  text ".VariantName" at 5058,-434 h60
  text "ASSEMBLY VARIANT:" at 6097,-434 h60
  text ".VersionControl_RevNumber" at 1035.5,-656.17 h60
  text "SVN REV:" at 1541.5,-656.17 h60
  text ".PCB_Rev" at 2088,-656.17 h60
  text "REV:" at 2379.5,-656.17 h60
  text ".PRJ_Number" at 3224,-656.17 h60
  text "BOARD #:" at 3769.5,-656.17 h60
  text "PCB VIEWED FROM BOTTOM SIDE" at 6246,-656.17 h60
  text ".TID" at 3224,-859.5 h60
  text "TID #:" at 3769.5,-859.5 h60
  text "TEXAS INSTRUMENTS" at 904.5,-1064.84 h60
  text ".Print_Time" at 2169,-1064.84 h60
  text ".Print_Date" at 2898,-1064.84 h60
  text "GENERATED    :" at 3767.5,-1064.84 h60
  text ".plot_File_Name" at 5440.5,-1064.84 h60
  text "PLOT NAME =" at 6246,-1064.84 h60
M9 Title Sheet:
  drawing of 57 lines, arcs and shapes, not listed
  text "1" at 739.84,8036.5 h70
  text "2" at 3235.5,8036.5 h70
  text "3" at 5724.84,8036.5 h70
  text "4" at 8231.51,8036.5 h70
  text "5" at 10730.5,8036.5 h70
  text "6" at 13235.5,8036.5 h70
  text "A" at -416.5,6893.5 h70
  text "A" at 14383.5,6893.5 h70
  text "B" at -416.5,4513.5 h70
  text "B" at 14383.5,4513.5 h70
  text "C" at -416.5,2138.5 h70
  text "C" at 14383.5,2138.5 h70
  text "PROJECT TITLE:" at 11343.5,277.5 h45
  text ".PRJ_Title" at 11393.5,144.17 h70
  text "DESIGNED FOR:" at 11343.5,-23.5 h45
  text ".PRJ_Customer" at 11393.5,-163.5 h70
  text "D" at -416.5,-231.5 h70
  text "D" at 14383.5,-231.5 h70
  text "FILE NAME:" at 11343.5,-323.5 h45
  text ".PCB_File_Name_No_Path" at 11393.5,-443.5 h70
  text "Texas Instruments (TI) and/or its licensors do not warrant the accuracy or completeness of this specification" at 6374,-605.34 h45
  text "ENGINEER:" at 11343.5,-613.5 h45
  text "LAYOUT BY:" at 12848.5,-613.5 h45
  text "or any information contained therein. TI and/or its licensors do not warrant that this design will meet" at 6329.01,-718 h45
  text ".PRJ_Engineer" at 11393.5,-768.49 h70
  text ".PCB_Layout" at 12899,-768.49 h70
  text "the specifications, will be suitable for your application or fit for any particular purpose, or will operate in" at 6329.01,-830.67 h45
  text ".Layer_Name" at 577,-858.49 h60
  text "ALTIUM DESIGNER VERSION:" at 12848.5,-923.5 h45
  text "an implementation. TI and/or its licensors do not warrant that the design is production worthy. You should" at 6329.01,-943.33 h45
  text "completely validate and test your design implementation to confirm the system functionality for your application." at 6374,-1056 h45
  text ".print_Scale" at 11393.5,-1056.83 h70
  text ".Application_BuildNumber" at 12899,-1056.83 h70
  text "1" at 739.84,-1263.5 h70
  text "2" at 3235.5,-1263.5 h70
  text "3" at 5724.84,-1263.5 h70
  text "4" at 8231.51,-1263.5 h70
  text "5" at 10730.5,-1263.5 h70
  text "6" at 13235.5,-1263.5 h70
M10 Fab Notes:
  drawing of 189 lines, arcs and shapes, not listed
  text "DESIGN INFORMATION" at 12382.02,6356.17 h60
  text "MIN. TRACK WIDTH:" at 11737.46,6224.05 h60
  text "8" at 12833.7,6224.05 h60
  text "MIL" at 12988.46,6224.05 h60
  text "MIN. CLEARANCE:" at 11737.46,6099.92 h60
  text "0.2" at 12773.7,6099.93 h60
  text "mm" at 12988.46,6099.92 h60
  text "MIN. VIA PAD SIZE:" at 11737.46,5975.8 h60
  text "24" at 12803.71,5975.8 h60
  text "MIL" at 12988.46,5975.8 h60
  text "0.05mm (2MIL)" at 12432.46,5845.9 h60
  text "MINIMUM ANNULAR RING" at 11408.23,5837.67 h60
  text "EXTERNAL" at 13140.46,5837.67 h60
  text "PER" at 11608.23,5727.55 h60
  text "IPC-D-275 CLASS 2 LEVEL C" at 11828.23,5727.54 h60
  text "MIL, HOLES" at 13316.46,5627.07 h60
  text "+/-" at 12924,5618.48 h60
  text "+/-" at 13778,5618.48 h60
  text "REGISTRATION TOLERANCES:" at 11408.23,5617.42 h60
  text "METAL" at 12608,5617.42 h60
  text "5" at 13184.2,5617.42 h60
  text "3" at 14017.2,5617.42 h60
  text "MIL" at 14133.46,5617.42 h60
  text "HOLE SIZE TOLERANCE (UNLESS OTHERWISE SPECIFIED):" at 11408.23,5519.1 h60
  text "+/-" at 13778,5516.23 h60
  text "3" at 14017.2,5515.17 h60
  text "MIL" at 14133.46,5515.17 h60
  text "MATERIAL:" at 11333.46,5377.52 h60
  text "FR-4 High Tg" at 12319.9,5249 h60
  text "X" at 12175.46,5241.01 h60
  text "FR-408" at 11754.46,5236.49 h60
  text "OTHER" at 13242.46,5236.49 h60
  text "62 MIL (1.6mm) +/-10%" at 12074.56,5093.46 h60
  text "X" at 11954.46,5091.01 h60
  text "THICKNESS:" at 11408.23,5085.24 h60
  text "OTHER" at 13359.46,5085.24 h60
  text "TOLERANCE:" at 11408.23,4946.92 h60
  text "X" at 12256.46,4946.92 h60
  text "ANSI IPC-6012 TYPE 3 CLASS 2" at 12434.48,4946.92 h60
  text "OTHER +/-" at 12434.46,4802.73 h60
  text "BOW & TWIST:" at 11408.23,4657.54 h60
  text "X" at 12256.46,4657.54 h60
  text "ANSI IPC-6012 TYPE 3 CLASS 2" at 12434.48,4657.54 h60
  text "OTHER +/-" at 12434.46,4510.85 h60
  text "DRILLING:" at 11333.46,4380.23 h60
  text "NC_DRILL FILES" at 13094.46,4275.04 h60
  text "REFERENCE:" at 11408.23,4271.1 h60
  text "X" at 12065.46,4271.01 h60
  text "AS SHOWN" at 12243.46,4271.1 h60
  text "X" at 12966.46,4271.1 h60
  text "OTHER" at 13392.46,4128.85 h60
  text "PTH COPPER THICKNESS:" at 11407.91,4125.32 h60
  text "X" at 12547.14,4125.32 h60
  text "20-30 um" at 12675.14,4125.32 h60
  text "BOARD FINISH:" at 11333.46,3977.73 h60
  text "SILKSCREEN:" at 11488.68,3867.6 h60
  text "X" at 12446.46,3867.6 h60
  text "TOP" at 12563.46,3867.6 h60
  text "X" at 12956.46,3867.6 h60
  text "BOTTOM" at 13074.46,3867.6 h60
  text "SILKSCREEN COLOR:" at 11488.68,3712.41 h60
  text "X" at 12445.46,3712.41 h60
  text "WHITE" at 12563.46,3712.41 h60
  text "OTHER" at 13074.46,3712.41 h60
  text "X" at 12576.46,3568.96 h60
  text "GREEN" at 12694.46,3568.96 h60
  text "OTHER" at 13312.46,3568.96 h60
  text "SOLDER RESIST COLOR:" at 11488.68,3562.1 h60
  text "X" at 12576.46,3414.71 h60
  text "MATTE" at 12694.46,3414.71 h60
  text "SEMI-GLOSS" at 13312,3414.07 h60
  text "IMMERSION GOLD (ENIG)" at 12394.46,3241.94 h60
  text "ENEPIG" at 13732,3234.72 h60
  text "SURFACE FINISH:" at 11333.46,3233.72 h60
  text "X" at 12216.46,3233.72 h60
  text "IMM. TIN/SILVER OR EQUIV" at 11663,3096.4 h60
  text "OTHER" at 13094.46,3092.47 h60
  text "ARRAY/PANEL:" at 11333.46,2937.09 h60
  text "CUT AND TRIM PER M1 BOARD OUTLINE" at 12394.46,2928.87 h60
  text "N.C. ROUTE" at 12394.46,2792.9 h60
  text "X" at 13082.46,2792.9 h60
  text "V. SCORE" at 13260.46,2792.9 h60
  text "CERTIFICATION:" at 11333.46,2663.77 h60
  text "MATERIALS AND WORKMANSHIP FOR ALL PCBS" at 12058.46,2663.77 h60
  text "TO MEET OR EXCEED THE REQUIREMENTS OF:" at 12058.46,2569.71 h60
  text "X" at 11695.97,2441.08 h60
  text "ANSI IPC-A-600F CLASS ->" at 11823.96,2441.08 h60
  text "X" at 13471.97,2441.08 h60
  text "2" at 13581.96,2441.08 h60
  text "1" at 13266.96,2439.58 h60
  text "3" at 13935.96,2439.58 h60
  text "X" at 12507.97,2293.39 h60
  text "RoHS" at 12635.96,2293.39 h60
  text "OTHER" at 13280.36,2293.39 h60
  text "PER ORDER" at 13677.42,2293.39 h60
  text "ALL BOARDS MUST MEET OR EXCEED UL94-V0 REQUIREMENTS." at 11361,2139.57 h60
  text "PCB MUST BEAR THE UL94V-0 UL REGISTERED MATERIAL ID NUMBER" at 11361,2023.5 h60
  text "ADDITIONAL REQUIREMENTS:" at 11333.46,1854.08 h60
  text "MICROSECTION:" at 11408.23,1746.95 h60
  text "YES" at 12313.96,1746.95 h60
  text "REQUIRED" at 13175.46,1602.62 h60
  text "BARE BOARD ELEC. TEST:" at 11408.23,1599.76 h60
  text "NONE" at 12713.96,1599.76 h60
  text "X" at 13057.46,1599.76 h60
  text "PER ORDER" at 13767.46,1599.76 h60
  text "XX MIL VIAS REQUIRE NON-CONDUCTIVE FILL AND PLANARIZE" at 11576.38,1394.82 h59
  text "XX MIL VIAS REQUIRE CONDUCTIVE FILL AND PLANARIZE" at 11584.38,1290.84 h60
  text "OUTER XX MIL TRACES REQUIRE 50 OHM SINGLE-ENDED IMPEDANCE" at 11583.39,1127.46 h58
  text "LAYER 2 & 3 (INNER LAYERS) XX MIL WIDE, XX MIL SPACE / TRACES REQUIRE 100 OHM DIFFERENTIAL IMPEDANCE" at 11575.39,891.74 h60
  text ".Layer_Name" at 577,-858.49 h60
M11 Gerber Information:
  lines w10: -292,-930.17 6308,-930.17 ; -292,-726.83 6310,-726.83 ; -292,-523.5 -292,-1133.5 3713,-1133.5 6310,-1133.5 6310,-523.5 -291.5,-523.5 -291.5,-1133.5 1284,-1133.5 ; 2173,-1133.5 2173,-523.5 ; 3440,-726.83 3440,-523.5 ; 4280,-726.83 4280,-523.5 ; 4902,-1140 4902,-937.17
  text "ALL ARTWORK VIEWED FROM TOP SIDE" at -228.5,-655.67 h60
  text "BOARD #:" at 2248,-655.67 h60
  text ".PRJ_Number" at 2793.5,-655.67 h60
  text "REV:" at 3638,-655.67 h60
  text ".PCB_Rev" at 3929.5,-655.67 h60
  text "SVN REV:" at 4476,-655.67 h60
  text ".VersionControl_RevNumber" at 4982,-655.67 h60
  text "LAYER NAME =" at -228.5,-858.49 h60
  text "TID #:" at 2248,-859 h60
  text ".TID" at 2793.5,-859 h60
  text "PLOT NAME =" at -228.5,-1064.34 h60
  text ".plot_File_Name" at 577,-1064.34 h60
  text "GENERATED    :" at 2250,-1064.34 h60
  text ".Print_Date" at 3119.5,-1064.34 h60
  text ".Print_Time" at 3848.5,-1064.34 h60
  text "TEXAS INSTRUMENTS" at 5113,-1064.34 h60
M12 Stackup:
  drawing of 295 lines, arcs and shapes, not listed
  text "Layer" at 9811.59,7784.94 h60
  text "Name" at 10221.51,7784.94 h60
  text "Material" at 11161.25,7784.94 h60
  text "Thickness" at 12021.02,7784.94 h60
  text "Constant" at 12670.85,7784.94 h60
  text "Board Layer Stack" at 13240.71,7784.94 h60
  text "1" at 9811.59,7664.94 h60
  text "Top Overlay" at 10221.51,7664.94 h60
  text "2" at 9811.59,7544.94 h60
  text "Top Solder" at 10221.51,7544.94 h60
  text "Solder Resist" at 11161.25,7544.94 h60
  text "0.40mil" at 12021.02,7544.94 h60
  text "3.5" at 12670.85,7544.94 h60
  text "3" at 9811.59,7424.94 h60
  text "Top Layer" at 10221.51,7424.94 h60
  text "Copper" at 11161.25,7424.94 h60
  text "1.40mil" at 12021.02,7424.94 h60
  text "4" at 9811.59,7304.94 h60
  text "Dielectric 2" at 10221.51,7304.94 h60
  text "10.00mil" at 12021.02,7304.94 h60
  text "4.2" at 12670.85,7304.94 h60
  text "5" at 9811.59,7184.94 h60
  text "Signal Layer 1" at 10221.51,7184.94 h60
  text "Copper" at 11161.25,7184.94 h60
  text "1.42mil" at 12021.02,7184.94 h60
  text "6" at 9811.59,7064.94 h60
  text "Dielectric1" at 10221.51,7064.94 h60
  text "FR-4" at 11161.25,7064.94 h60
  text "59.20mil" at 12021.02,7064.94 h60
  text "4.8" at 12670.85,7064.94 h60
  text "7" at 9811.59,6944.94 h60
  text "Signal Layer 2" at 10221.51,6944.94 h60
  text "Copper" at 11161.25,6944.94 h60
  text "1.42mil" at 12021.02,6944.94 h60
  text "8" at 9811.59,6824.94 h60
  text "Dielectric 3" at 10221.51,6824.94 h60
  text "10.00mil" at 12021.02,6824.94 h60
  text "4.2" at 12670.85,6824.94 h60
  text "9" at 9811.59,6704.94 h60
  text "Bottom Layer" at 10221.51,6704.94 h60
  text "Copper" at 11161.25,6704.94 h60
  text "1.40mil" at 12021.02,6704.94 h60
  text "10" at 9811.59,6584.94 h60
  text "Bottom Solder" at 10221.51,6584.94 h60
  text "Solder Resist" at 11161.25,6584.94 h60
  text "0.40mil" at 12021.02,6584.94 h60
  text "3.5" at 12670.85,6584.94 h60
  text "11" at 9811.59,6464.94 h60
  text "Bottom Overlay" at 10221.51,6464.94 h60
  text ".Layer_Name" at 577,-858.49 h60
M13 Component Bodies Top:
  text ".Layer_Name" at 577,-858.49 h60
M14 Component Bodies Bottom:
  text ".Layer_Name" at 577,-858.49 h60
M15 Courtyards Top:
  text ".Layer_Name" at 577,-858.49 h60
M16 Courtyards Bottom:
  text ".Layer_Name" at 577,-858.49 h60
Drill Drawing:
  circle w10: c5363.72,3314.28 r27.63
  lines w10: 5336.09,2927.51 5349.9,2927.51 5363.72,2913.7 5377.53,2927.51 5391.34,2927.51 5377.53,2941.32 5391.34,2955.14 5377.53,2955.14 5363.72,2968.95 5349.9,2955.14 5336.09,2955.14 5349.9,2941.32 5336.09,2927.51 ; 5336.09,3093.27 5391.34,3093.27 5363.72,3038.02 5336.09,3093.27 ; 5336.09,3162.34 5391.34,3162.34 5391.34,3217.59 5336.09,3217.59 5336.09,3162.34
  lines w12: 5286,2876.4 8517.49,2876.4 ; 5286,3373.68 8517.49,3373.68 ; 5623.86,2752.08 5623.86,3498 ; 5955.86,2752.08 5955.86,3498 ; 6592.43,2752.08 6592.43,3498 ; 6851.57,2752.08 6851.57,3498 ; 7226.72,2752.08 7226.72,3498 ; 7951.05,2752.08 7951.05,3498 ; 5286,2752.08 8517.49,2752.08 8517.49,3498 5286,3498 5286,2752.08
  text "Symbol" at 5360.59,3410.98 h72
  text "Quantity" at 5661.16,3410.98 h72
  text "Finished Hole Size" at 5993.16,3410.98 h72
  text "Plated" at 6629.72,3410.98 h72
  text "Hole Type" at 6888.86,3410.98 h72
  text "Drill Layer Pair" at 7264.02,3410.98 h72
  text "Hole Tolerance" at 7988.35,3410.98 h72
  text "26" at 5661.16,3286.66 h60
  text "12.00mil (0.305mm)" at 5993.16,3286.66 h60
  text "PTH" at 6629.72,3286.66 h60
  text "Round" at 6888.86,3286.66 h60
  text "Top Layer - Bottom Layer" at 7264.02,3286.66 h60
  text "14" at 5661.16,3162.34 h60
  text "40.16mil (1.020mm)" at 5993.16,3162.34 h60
  text "PTH" at 6629.72,3162.34 h60
  text "Round" at 6888.86,3162.34 h60
  text "Top Layer - Bottom Layer" at 7264.02,3162.34 h60
  text "9" at 5661.16,3038.02 h60
  text "40.95mil (1.040mm)" at 5993.16,3038.02 h60
  text "PTH" at 6629.72,3038.02 h60
  text "Round" at 6888.86,3038.02 h60
  text "Top Layer - Bottom Layer" at 7264.02,3038.02 h60
  text "2" at 5661.16,2913.7 h60
  text "124.80mil (3.170mm)" at 5993.16,2913.7 h60
  text "PTH" at 6629.72,2913.7 h60
  text "Round" at 6888.86,2913.7 h60
  text "Top Layer - Bottom Layer" at 7264.02,2913.7 h60
  text "51 Total" at 5661.16,2789.38 h60
  text ".Layer_Name" at 577,-858.49 h60
M17 Embedded Cavity:
  text ".Layer_Name" at 577,-858.49 h60
M18 Embedded Assembly:
  text ".Layer_Name" at 577,-858.49 h60
M19 Embedded Keepout:
  text ".Layer_Name" at 577,-858.49 h60

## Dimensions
0,-400 to 1000,-400 on M2 Board Dimensions
0,0 to 0,1400 on M2 Board Dimensions
0,0 to 1800,0 on M2 Board Dimensions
